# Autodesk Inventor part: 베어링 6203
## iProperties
IsCustomPart: 0
Created: 2009-02
Part Number: 베어링 6203
Material: Steel, Mild
Description: 깊은 그루브 볼 베어링
Document SubType Name: Modeling
Standard: KS B 2023
Designer: SeoGD™ [www.esajin.kr]
Standards Organization: KS
Language: ko-KR
Size Designation: 6203 - 17 x 40 x 12
Categories: <MemberInstance><Categories><Category DisplayName="샤프트 부품" InternalName="7f7aeb1f-a693-4053-b835-cee3144e0d98" Mnemonic="SHFT"><Category DisplayName="베어링" Inter
Density: 1 g/cm^3
Author: SeoGD™ [www.esajin.kr]
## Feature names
1. IDS_ARRAYBALL[SIMPL:T] [Circular Pattern]
